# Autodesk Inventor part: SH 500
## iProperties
Shininess: 64.0
Length Units: 11272
Angle Units: 11279
Time Units: 11290
Mass Units: 11286
Length Display Precision: 3
Angle Display Precision: 2
Manager: Cory McConnell
Company: Mechanix Design Solutions
Created: 2002-07
Part Number: SH 500
Material: Steel, High Strength Low Alloy
Description: BROWNING® QD BUSHING
Document SubType Name: Modeling
Designer: CM
Density: 10.49
Volumn: 2.304646865681294
Area: 8.437628188859923
PropertySet Name: Model Information
Control State: 0
Master: False
Checked Out: False
Author: CM
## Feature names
1. Revolution2
2. Extrusion2
3. Extrusion3
4. Hole1
5. Hole2
6. Circular Pattern1
7. Hole3
